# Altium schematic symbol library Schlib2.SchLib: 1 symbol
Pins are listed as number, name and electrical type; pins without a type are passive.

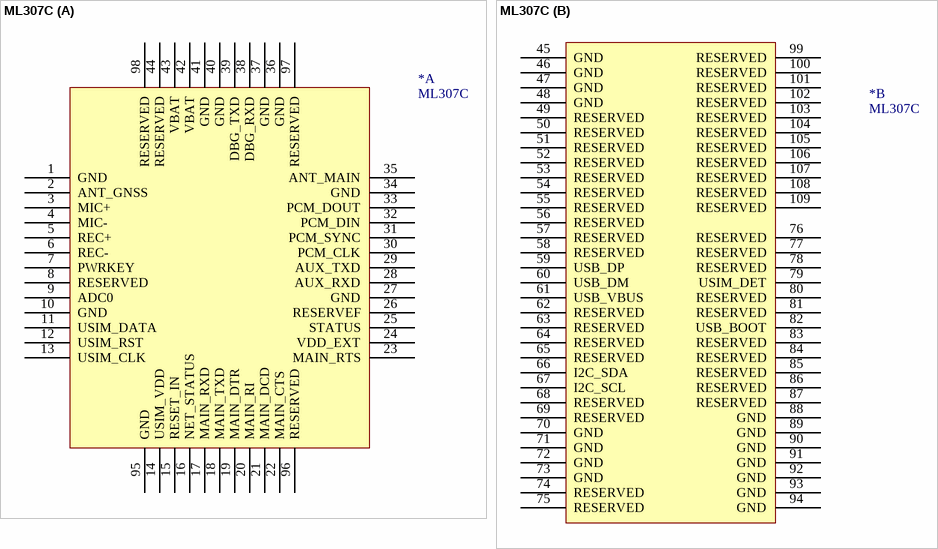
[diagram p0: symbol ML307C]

## ML307C
designator *
footprint ML307C (Footprint not found)
part A pins: 1 GND (power), 2 ANT_GNSS, 3 MIC+, 4 MIC-, 5 REC+, 6 REC-, 7 PWRKEY, 8 RESERVED, 9 ADC0, 10 GND (power), 11 USIM_DATA, 12 USIM_RST, 13 USIM_CLK, 14 USIM_VDD, 15 RESET_IN, 16 NET_STATUS, 17 MAIN_RXD, 18 MAIN_TXD, 19 MAIN_DTR, 20 MAIN_RI, 21 MAIN_DCD, 22 MAIN_CTS, 23 MAIN_RTS, 24 VDD_EXT, 25 STATUS, 26 RESERVEF, 27 GND (power), 28 AUX_RXD, 29 AUX_TXD, 30 PCM_CLK, 31 PCM_SYNC, 32 PCM_DIN, 33 PCM_DOUT, 34 GND (power), 35 ANT_MAIN, 36 GND (power), 37 GND (power), 38 DBG_RXD, 39 DBG_TXD, 40 GND (power), 41 GND (power), 42 VBAT (power), 43 VBAT (power), 44 RESERVED, 95 GND (power), 96 RESERVED, 97 RESERVED, 98 RESERVED
part B pins: 45 GND, 46 GND, 47 GND, 48 GND, 49 RESERVED, 50 RESERVED, 51 RESERVED, 52 RESERVED, 53 RESERVED, 54 RESERVED, 55 RESERVED, 56 RESERVED, 57 RESERVED, 58 RESERVED, 59 USB_DP, 60 USB_DM, 61 USB_VBUS, 62 RESERVED, 63 RESERVED, 64 RESERVED, 65 RESERVED, 66 I2C_SDA, 67 I2C_SCL, 68 RESERVED, 69 RESERVED, 70 GND, 71 GND, 72 GND, 73 GND, 74 RESERVED, 75 RESERVED, 76 RESERVED, 77 RESERVED, 78 RESERVED, 79 USIM_DET, 80 RESERVED, 81 RESERVED, 82 USB_BOOT, 83 RESERVED, 84 RESERVED, 85 RESERVED, 86 RESERVED, 87 RESERVED, 88 GND, 89 GND, 90 GND, 91 GND, 92 GND, 93 GND, 94 GND, 99 RESERVED, 100 RESERVED, 101 RESERVED, 102 RESERVED, 103 RESERVED, 104 RESERVED, 105 RESERVED, 106 RESERVED, 107 RESERVED, 108 RESERVED, 109 RESERVED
